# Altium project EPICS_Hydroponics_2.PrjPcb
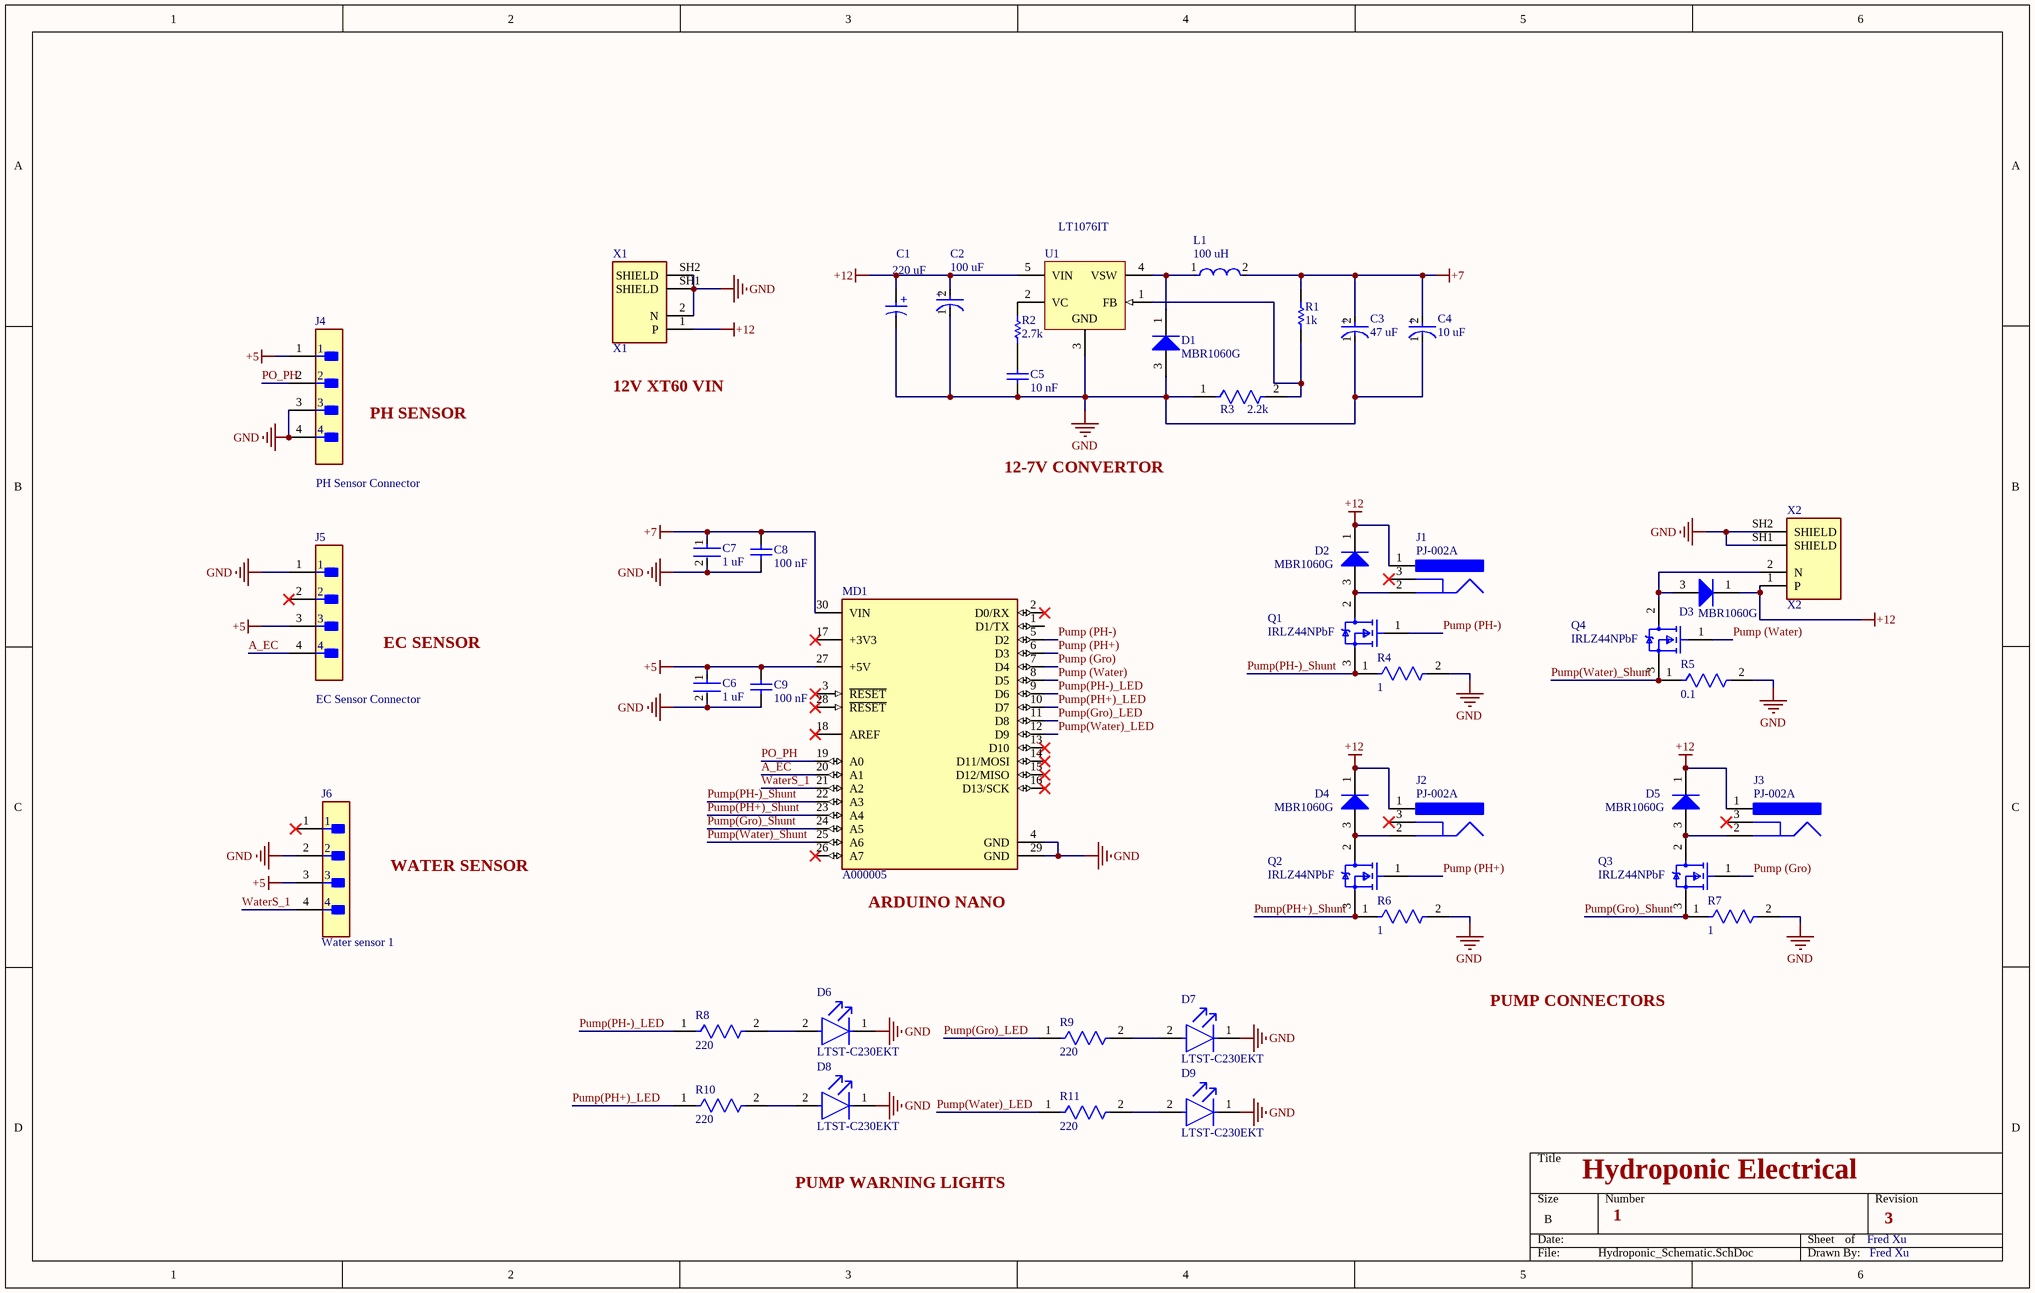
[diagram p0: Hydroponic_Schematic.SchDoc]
1 sheet, 44 parts. Net scope: global (net labels, ports and power ports of the same name join across sheets).
Board file: Hydroponic_PCB.PcbDoc

## Sheet Hydroponic_Schematic.SchDoc
size B; SheetNumber: 1; SheetTotal: 1

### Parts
C1  220 uF  [WCAP-ASLL_D6.3H7.7]
C2  100 uF  [FP-TGV10X10_5-MFG]
C3  47 uF  [FP-UUX1H470MNL6GS-MFG]
C4  10 uF  [FP-EDK9B-MFG]
C5  10 nF  [CAPC1608X87X35LL15T15]
C6  1 uF  [FP-CC0805-0_85-MFG]
C7  1 uF  [FP-CC0805-0_85-MFG]
C8  100 nF  [CAPC2013X140X50LL20T25]
C9  100 nF  [CAPC2013X140X50LL20T25]
D1  MBR1060G  [ONSC-TO-220-2-221B-04_E]
D2  MBR1060G  [ONSC-TO-220-2-221B-04_E]
D3  MBR1060G  [ONSC-TO-220-2-221B-04_E]
D4  MBR1060G  [ONSC-TO-220-2-221B-04_E]
D5  MBR1060G  [ONSC-TO-220-2-221B-04_E]
D6  LTST-C230EKT  [FP-LTST-C230EKT-MFG]
D7  LTST-C230EKT  [FP-LTST-C230EKT-MFG]
D8  LTST-C230EKT  [FP-LTST-C230EKT-MFG]
D9  LTST-C230EKT  [FP-LTST-C230EKT-MFG]
J1  PJ-002A  [CUI-PJ-002A_V]
J2  PJ-002A  [CUI-PJ-002A_V]
J3  PJ-002A  [CUI-PJ-002A_V]
J4  PH Sensor Connector  [FP-B4B-XH-AM_LF_SN-MFG]
J5  EC Sensor Connector  [FP-B4B-XH-AM_LF_SN-MFG]
J6  Water sensor 1  [FP-B4B-XH-AM_LF_SN-MFG]
L1  100 uH  [FP-LQM21DH_70-IPC_C]
MD1  A000005  [FP-A000005-MFG]
Q1  IRLZ44NPbF  [FP-PG-TO220-3-MFG]
Q2  IRLZ44NPbF  [FP-PG-TO220-3-MFG]
Q3  IRLZ44NPbF  [FP-PG-TO220-3-MFG]
Q4  IRLZ44NPbF  [FP-PG-TO220-3-MFG]
R1  1k  [RESC2013X60X35LL10T20]
R2  2.7k  [RESC0603(1608)_M]
R3  2.2k  [FP-AC0805-MFG]
R4  1  [FP-CRCW2512-e3-IPC_C]
R5  0.1  [FP-CSRN2010-IPC_A]
R6  1  [FP-CRCW2512-e3-IPC_C]
R7  1  [FP-CRCW2512-e3-IPC_C]
R8  220  [FP-RMCF0805-IPC_A]
R9  220  [FP-RMCF0805-IPC_A]
R10  220  [FP-RMCF0805-IPC_A]
R11  220  [FP-RMCF0805-IPC_A]
U1  LT1076IT  [LT-T-5-S]
X1  X1  [PCBComponent_1]
X2  X2  [PCBComponent_1]

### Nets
+5: C6.1 C9.2 J4.1 J5.3 J6.3 MD1.27(+5V)
+7: C3.2(A) C4.2(A) C7.1 C8.2 L1.2 MD1.30(VIN) R1.2
+12: C1.1(P) C2.2(A) D2.1(K) D3.1(K) D4.1(K) D5.1(K) J1.1 J2.1 J3.1 U1.5(VIN) X1.1(P) X2.1(P)
GND: C1.2(N) C2.1(C) C3.1(C) C4.1(C) C5.2 C6.2 C7.2 C8.1 C9.1 D1.3(A) D6.1(C) D7.1(C) D8.1(C) D9.1(C) J4.3 J4.4 J5.1 J6.2 MD1.4(GND) MD1.29(GND) R3.1 R4.2 R5.2 R6.2 R7.2 U1.3(GND) X1.2(N) X1.SH1(SHIELD) X1.SH2(SHIELD) X2.SH1(SHIELD) X2.SH2(SHIELD)
A_EC: J5.4 MD1.20(A1)
PO_PH: J4.2 MD1.19(A0)
Pump (Gro): MD1.7(D4) Q3.1(G)
Pump (PH+): MD1.6(D3) Q2.1(G)
Pump (PH-): MD1.5(D2) Q1.1(G)
Pump (Water): MD1.8(D5) Q4.1(G)
Pump(Gro)_LED: MD1.11(D8) R9.1
Pump(Gro)_Shunt: MD1.24(A5) Q3.3(S) R7.1
Pump(PH+)_LED: MD1.10(D7) R10.1
Pump(PH+)_Shunt: MD1.23(A4) Q2.3(S) R6.1
Pump(PH-)_LED: MD1.9(D6) R8.1
Pump(PH-)_Shunt: MD1.22(A3) Q1.3(S) R4.1
Pump(Water)_LED: MD1.12(D9) R11.1
Pump(Water)_Shunt: MD1.25(A6) Q4.3(S) R5.1
WaterS_1: J6.4 MD1.21(A2)
NetC5_1: C5.1 R2.1
NetD1_1: D1.1(K) L1.1 U1.4(VSW)
NetD2_3: D2.3(A) J1.2 Q1.2(D)
NetD3_3: D3.3(A) Q4.2(D) X2.2(N)
NetD4_3: D4.3(A) J2.2 Q2.2(D)
NetD5_3: D5.3(A) J3.2 Q3.2(D)
NetD6_2: D6.2(A) R8.2
NetD7_2: D7.2(A) R9.2
NetD8_2: D8.2(A) R10.2
NetD9_2: D9.2(A) R11.2
NetR1_1: R1.1 R3.2 U1.1(FB)
NetR2_2: R2.2 U1.2(VC)

Not connected (* = marked no-connect by the designer): J1 3*; J2 3*; J3 3*; J5 2*; J6 1*; MD1 1(D1/TX) 2(D0/RX)* 3(~{RESET})* 13(D10)* 14(D11/MOSI)* 15(D12/MISO)* 16(D13/SCK)* 17(+3V3)* 18(AREF)* 26(A7)* 28(~{RESET})*

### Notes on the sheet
- PH SENSOR
- (near X1) 12V XT60 VIN
- 12-7V CONVERTOR
- EC SENSOR
- WATER SENSOR
- (near MD1) ARDUINO NANO
- PUMP CONNECTORS
- Hydroponic Electrical
- PUMP WARNING LIGHTS
- 1
- Fred Xu
- 3

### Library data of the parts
C1 = CMP-03913-53914500-3: Ripple Current: 280mA; ESR (Equivalent Series Resistance): 246.927mΩ; Life (Hours): 2000hours; Material: Aluminium; Polarity: Polar; Insulation Resistance: 454.545kΩ; Impedance: 360mΩ; Leakage Current: 13.86µA; Voltage Rating: 6.3V; Tolerance: 20%; Capacitance: 220µF
C2 = CMP-35376-000017-1: CAP ALUM 100UF 20% 35V SMD
C3 = CMP-12462-000056-1: CAP ALUM 47UF 20% 50V SMD; Ripple Current: 167mA; Dissipation Factor: 0.1%; Leakage Current: 70.5uA; Life (Hours): 2000Hour; Lead Diameter: 1.1mm
C4 = CMP-03015-000003-1: CAP ALUM 10UF 20% 35V SMD; Manufacturer: Kemet; Manufacturer Part Number: EDK106M035A9BAA; Dissipation Factor: 16%; Material: Aluminum; Leakage Current: 3.5uA; Ripple Current: 24mA; Life: 2000Hours
C5 = CMP-2006-03842-1: Manufacturer: Kemet; Part Number: C0603S103K4RACTU
C6 C7 = CMP-03422-000746-1: CAP CER 1UF 10V X5R 0805; Manufacturer: Yageo; Manufacturer Part Number: CC0805KKX5R6BB105; Material: Ceramic; Tolerance: 0.1
C8 C9 = CMP-2007-04740-1: Part Number: 08051C104M4Z2A; Manufacturer: AVX Interconnect / Elco
D1-D5 = CMP-1055-00607-1: SWITCHMODE(TM) Power Rectifier, 2-Pin TO-220, Pb-Free, Tube; Manufacturer: On Semiconductor; IFSM Max (A): 150; Configuration: Single
D6-D9 = CMP-22017-000030-1: LED RED CLEAR CHIP SMD; Forward Current: 30mA; Test Current: 10mA; Number of Elements: 1; Viewing Angle: 130°; Dominant Wavelength: 621nm; Forward Voltage: 2V; Lens Style: Diffused; Power Rating: 100mW; Reverse Voltage: 5V; Wavelength: 630nm; Luminous Intensity: 6mcd; Lens Color: Colorless
J1-J3 = CMP-2000-06895-2: Through Hole Right Angle DC Power Jack, 2.5 A, 2 mm Center Pin, 3 Position, -25 to 85 degC, RoHS, Bulk; Manufacturer: CUIInc.; Brand: CUI; Inside Contact Diameter: 2mm; Voltage Rating: 24V; Outside Contact Diameter: 6.5mm; Current Rating: 2.5A; Insulation Resistance: 50MOhms
J4-J6 = CMP-17439-000117-1: CONN HEADER VERT 4POS 2.5MM; Max Current Rating: 3A; Gender: Male; Contact Resistance: 20mR; Number of Positions: 4; Mated Stacking Heights: 9.8mm; Voltage Rating: 250V
L1 = CMP-06042-017057-1: Multilayer type Inductor for Power Lines for Automotive 100uH ±20% @1MHz, 160mA, Max DCR 4.095Ω, SRF 8MHz
MD1 = CMP-189986-000002-1: ARDUINO NANO ATMEGA328 EVAL BRD; Number of Bits: 8; Evaluation Kit: Yes; Operating Supply Voltage: 12V; Interface: I2C; Data Bus Width: 8b; Core Architecture: AVR
Q1-Q4 = CMP-32901-000488-1: MOSFET N-CH 55V 47A TO220AB; Turn-On Delay Time: 11ns; Gate to Source Voltage (Vgs): 16V; Element Configuration: Single; Rds On Max: 22mR; Turn-Off Delay Time: 26ns; Max Power Dissipation: 110W; Threshold Voltage: 2V; Drain to Source Resistance: 35mR; Input Capacitance: 1.7nF
R1 = CMP-2001-01418-1: Manufacturer: Yageo; Part Number: RC0805JR-131KL
R2 = CMP-1012-00084-1: 2K7 0.1W 5% 0603 (1608 Metric)  SMD; Case-EIA: 0603; Value: 2700.00 Ohm; Case-Metric: 1608
R3 = CMP-03412-037614-1: RES SMD 2.2K OHM 5% 1/8W 0805; Manufacturer Part Number: AC0805JR-072K2L; Manufacturer: Yageo; Voltage Rating: 150V; Value: 2.2KΩ; Automotive Grade: Grade 0; Tolerance: 0.05
R4 R6 R7 = CMP-02407-008720-1: RES Thick Film, 1Ω, 1%, 1W, 100ppm/°C, 2512; Resistance: 1R
R5 = CMP-26527-001368-1: Res Thick Film 2010 0.1Ω 1% 1W ±250ppm/°C Molded SMD Plastic T/R; Resistance: 100mR
R8-R11 = CMP-26527-006932-1: 220Ω ±5% 0.125W 0805 Thick Film Chip Resistor AEC-Q200 compliant; Resistance: 220R; Max Power Dissipation: 125mW; Temperature Coefficient: 200ppm/°C
U1 = CMP-0491-02059-1: Step-Down Switching Regulator, 5-pin FM (T-5), -40 to 85 degC; Manufacturer: Linear Technology; Number of Outputs: 1
X1 X2 = xt60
